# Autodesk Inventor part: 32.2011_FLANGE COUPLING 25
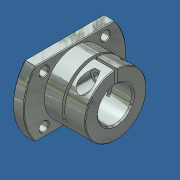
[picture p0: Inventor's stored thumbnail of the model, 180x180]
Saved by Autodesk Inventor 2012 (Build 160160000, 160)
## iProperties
Created: 2016-09
Part Number: 32.2011_FLANGE COUPLING 25
Material: Default
Document SubType Name: Modeling
Designer: Admin
Density: 1 g/cm^3
Author: Admin
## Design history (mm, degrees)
feature "Base1"
body "Solid1"
